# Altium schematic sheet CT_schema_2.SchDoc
size 296 x 169 mm
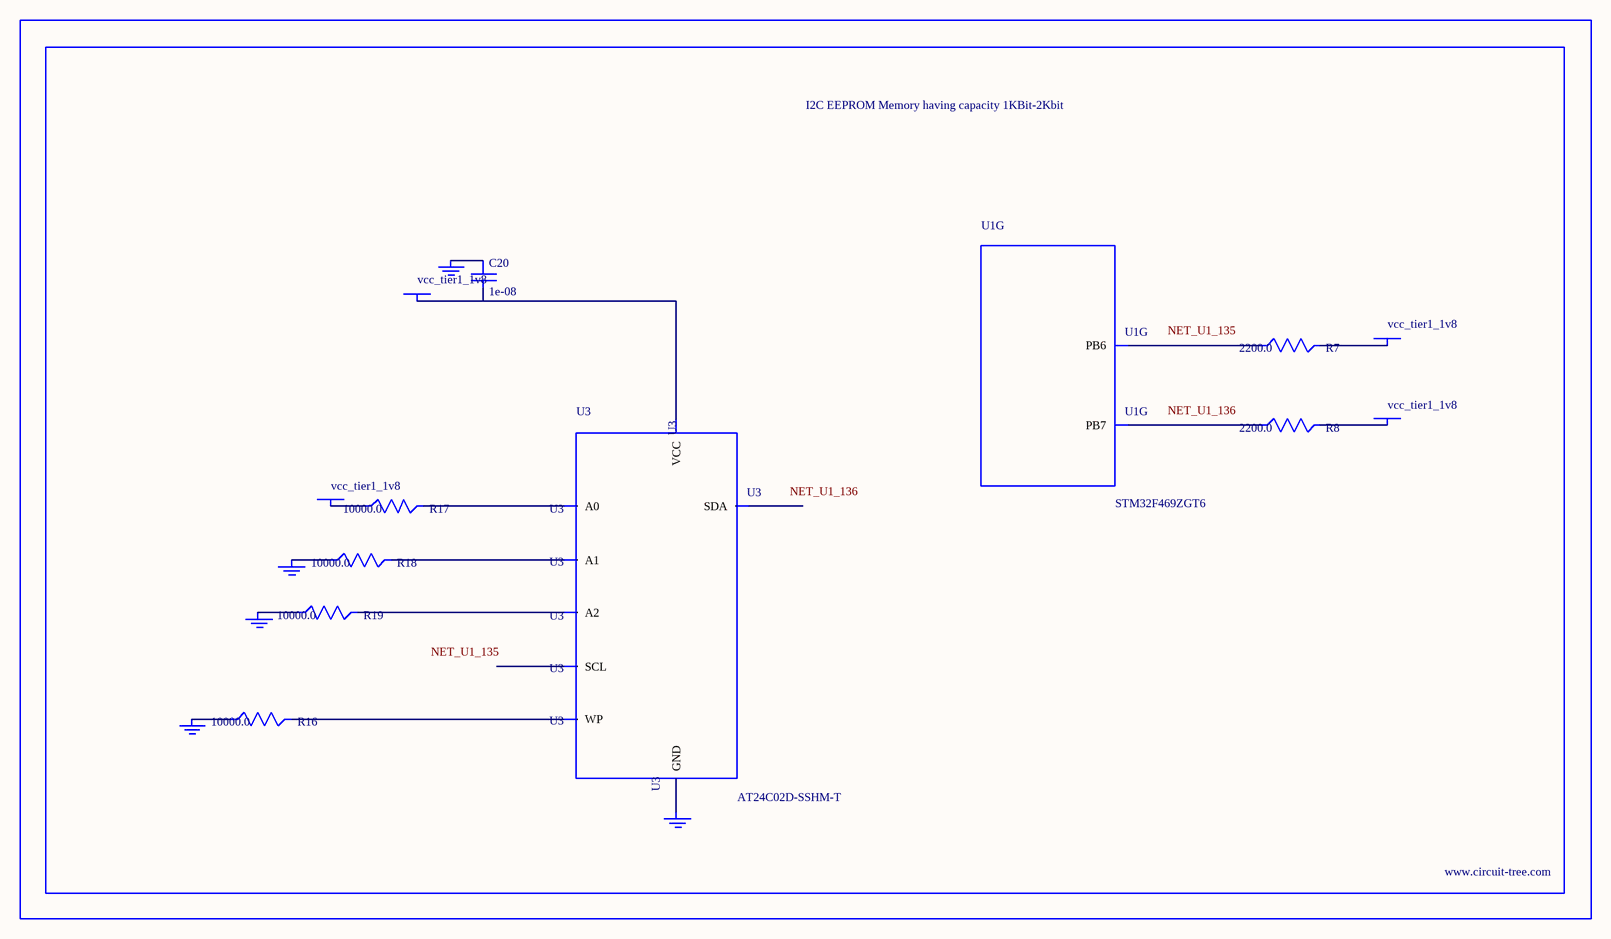
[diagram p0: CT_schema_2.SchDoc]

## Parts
BORDER1  (no value)
C20  1e-08  [C0402]
GND_INSTANCE_1_0  (no value)
GND_INSTANCE_1_1  (no value)
GND_INSTANCE_1_2  (no value)
GND_INSTANCE_1_3  (no value)
GND_INSTANCE_1_4  (no value)
POWER_INSTANCE_1_0  vcc_tier1_1v8
POWER_INSTANCE_1_1  vcc_tier1_1v8
POWER_INSTANCE_1_2  vcc_tier1_1v8
POWER_INSTANCE_1_3  vcc_tier1_1v8
R7  2200.0  [R0603]
R8  2200.0  [R0603]
R16  10000.0  [R0603]
R17  10000.0  [R0603]
R18  10000.0  [R0603]
R19  10000.0  [R0603]
U1  STM32F469ZGT6  [LQFP144]  (part G of 12)
U3  AT24C02D-SSHM-T  [AT24C02D]

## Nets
NetC20_1: C20.1 GND_INSTANCE_1_3.0(GND)
NetC20_2: C20.2 POWER_INSTANCE_1_1.0(PWR) U3.8(VCC)
NetGND_INSTANCE_1_0_0: GND_INSTANCE_1_0.0(GND) R18.1
NetGND_INSTANCE_1_1_0: GND_INSTANCE_1_1.0(GND) R19.1
NetGND_INSTANCE_1_2_0: GND_INSTANCE_1_2.0(GND) R16.1
NetGND_INSTANCE_1_4_0: GND_INSTANCE_1_4.0(GND) U3.4(GND)
NetPOWER_INSTANCE_1_0_0: POWER_INSTANCE_1_0.0(PWR) R17.1
NetPOWER_INSTANCE_1_2_0: POWER_INSTANCE_1_2.0(PWR) R7.2
NetPOWER_INSTANCE_1_3_0: POWER_INSTANCE_1_3.0(PWR) R8.2
NetR7_1: R7.1 U1.135(PB6)
NetR8_1: R8.1 U1.136(PB7)
NetR16_2: R16.2 U3.7(WP)
NetR17_2: R17.2 U3.1(A0)
NetR18_2: R18.2 U3.2(A1)
NetR19_2: R19.2 U3.3(A2)

Not connected (* = marked no-connect by the designer): U3 5(SDA) 6(SCL)

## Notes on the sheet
- Labels drawn without touching a wire or pin: NET_U1_135, NET_U1_136

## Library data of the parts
BORDER1 = BORDER_PAGE1
C20 = C0402C103K3RAC
GND_INSTANCE_1_0-GND_INSTANCE_1_4 = GND
POWER_INSTANCE_1_0-POWER_INSTANCE_1_3 = PWR
R7 R8 = RC0603JR-072K2L
R16-R19 = RC0603JR-0710KL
